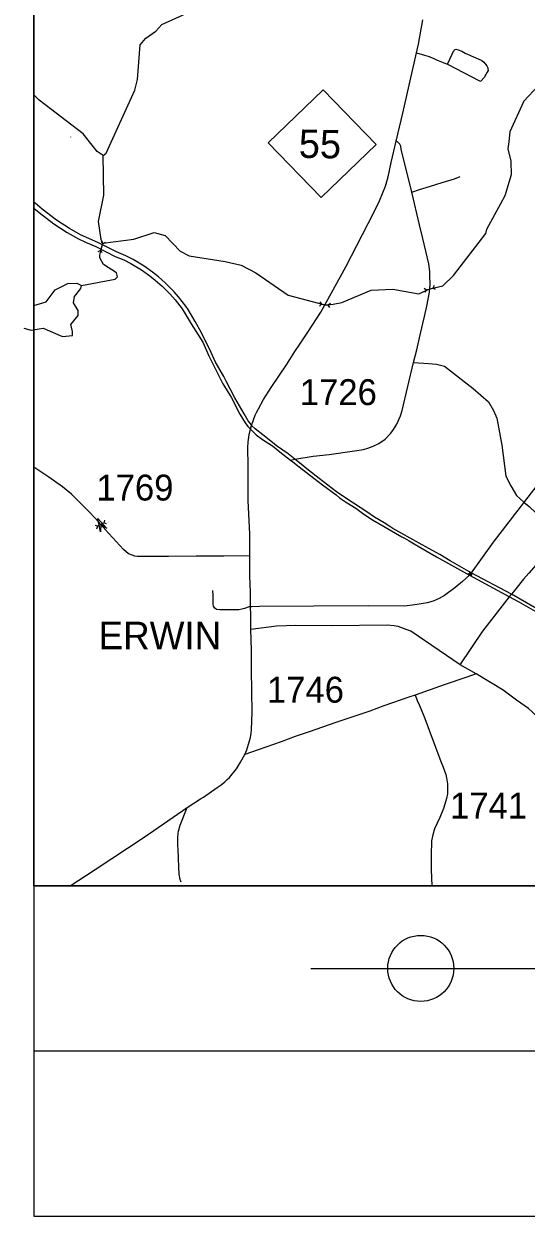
# Model space of a CAD drawing. Extents: x 0 to 2021, y 0 to 1321.
# Drawn here: x 316.9 to 408.2, y 888.1 to 1104.7 of the extents above; entities that cross this region are included whole.
import ezdxf

# ---------------------------------------------------------------- set-up
doc = ezdxf.new("R2010")
doc.units = 0
for name, color, linetype in [('Default', 7, 'Continuous'), ('Exist Hydro Stream or Body of Water', 7, 'Continuous'), ('Miscellaneous Lines', 7, 'Continuous'), ('Old_Level_26', 7, 'Continuous'), ('Scratch_Level_0', 7, 'Continuous'), ('Sheet Title CELL', 7, 'Continuous'), ('Text', 7, 'Continuous')]:
    doc.layers.add(name, color=color, linetype=linetype)

msp = doc.modelspace()

# ---------------------------------------------------------------- linework, layer by layer
at = {"layer": 'Default'}
for p, q in [((325.36, 1084.18), (325.36, 1084.13)), ((330.88, 1063.55), (331.23, 1064.72)), ((330.98, 1065.17), (331.23, 1064.72)), ((331.69, 1064.95), (331.23, 1064.72)), ((330.42, 1063.32), (330.88, 1063.55)), ((331.13, 1063.1), (330.88, 1063.55)), ((389.63, 1056.65), (390.07, 1056.38)), ((389.82, 1055.92), (390.07, 1056.38)), ((390.07, 1056.38), (391.25, 1056.68)), ((391.5, 1057.13), (391.25, 1056.68)), ((391.69, 1056.41), (391.25, 1056.68)), ((370.61, 1053.43), (371.01, 1053.75)), ((370.71, 1054.17), (371.01, 1053.75)), ((371.01, 1053.75), (372.22, 1053.58)), ((372.62, 1053.9), (372.22, 1053.58)), ((372.52, 1053.16), (372.22, 1053.58)), ((330.33, 1013.46), (331.42, 1014.02)), ((331.57, 1014.51), (331.42, 1014.02)), ((331.91, 1013.84), (331.42, 1014.02)), ((329.85, 1013.63), (330.33, 1013.46)), ((330.19, 1012.97), (330.33, 1013.46)), ((397.6, 1004.74), (397.79, 1004.76)), ((397.86, 1005.21), (397.94, 1005.04)), ((397.87, 1004.9), (398.28, 1004.67)), ((398.21, 1004.53), (398.29, 1004.36)), ((398.36, 1004.8), (398.55, 1004.82)), ((399.1, 986.58), (396.23, 988.25))]:
    msp.add_line(p, q, dxfattribs=at)
for points in [[(388.26, 1099.46), (388.6, 1101.01), (389.44, 1105.43)], [(384.57, 1083.38), (385.79, 1088.45), (388.26, 1099.46)], [(358.25, 1031.74), (358.58, 1032.59), (358.93, 1033.58), (359.2, 1034.11), (359.52, 1034.76), (360.45, 1036.46), (361.84, 1038.65), (363.34, 1040.86), (364.64, 1042.75), (366.18, 1045.15), (367.06, 1046.48), (368.61, 1048.84), (370.9, 1052.3), (375.45, 1060.53), (377.43, 1064.41), (380.49, 1070.44), (381.53, 1072.56), (382.61, 1075.22), (383.09, 1076.89), (383.68, 1079.48), (384.57, 1083.38)], [(343.97, 1056.26), (342.61, 1057.63), (341.36, 1058.73), (340.28, 1059.59), (338.74, 1060.67), (336.77, 1061.86), (335.42, 1062.55), (333.76, 1063.25), (330.34, 1065), (327.2, 1066.39), (325.22, 1067.49), (322.83, 1069.05), (320.22, 1071.05), (318.96, 1072.12), (318.71, 1072.35)], [(318.71, 1071.24), (319.7, 1070.41), (322.35, 1068.37), (324.8, 1066.78), (326.83, 1065.66), (328.08, 1065.06), (329.99, 1064.25), (333.52, 1062.44), (335.07, 1061.8), (336.37, 1061.14), (338.28, 1059.98), (339.78, 1058.93), (340.77, 1058.14), (342.04, 1057.03), (343.41, 1055.64)], [(343.41, 1055.64), (344.38, 1054.58), (345.67, 1052.9), (347.34, 1050.19), (349.43, 1046.87), (350.53, 1044.36), (352.57, 1040.26), (353.09, 1039.3), (354.58, 1036.89), (356.14, 1033.76), (357.12, 1032.18), (357.59, 1031.53), (358.08, 1031.06)], [(358.25, 1031.74), (358.03, 1032.15), (357.67, 1032.58), (356.92, 1033.86), (355.24, 1036.74), (353.71, 1039.66), (353.22, 1040.65), (351.69, 1043.34), (350.93, 1044.96), (349.19, 1048.54), (348.06, 1050.61), (346.74, 1052.78), (346.36, 1053.38), (345.02, 1055.11), (344.21, 1056.02), (343.97, 1056.26)], [(358.08, 1031.06), (358.25, 1031.74)], [(366.18, 1025.58), (364.97, 1026.6), (363.02, 1027.93), (360.31, 1030.05), (358.97, 1031.13), (358.25, 1031.74)], [(357.97, 1008.02), (357.99, 1011.97), (357.65, 1018.1), (357.66, 1019.8), (357.7, 1021.46), (357.7, 1024.38), (357.59, 1027.64), (357.64, 1028.74), (357.72, 1029.17), (357.87, 1030.05), (358.08, 1031.06)], [(358.08, 1031.06), (358.69, 1030.45), (359.14, 1030.05), (360.29, 1029.19), (362.12, 1028), (363.44, 1026.92), (365.36, 1025.45)], [(365.36, 1025.45), (366.18, 1025.58)], [(365.36, 1025.45), (365.78, 1025.12), (366.91, 1024.24), (369.6, 1022.13), (371.18, 1020.95), (373.69, 1019.14), (374.28, 1018.58), (375.39, 1017.83), (377.22, 1016.69), (378.69, 1015.61), (380.27, 1014.59), (385.61, 1011.47), (386.06, 1011.24), (386.91, 1010.77), (387.83, 1010.2), (388.9, 1009.6), (391.88, 1007.88), (395.19, 1006.03), (397.89, 1004.53), (405.18, 1000.57)], [(405.51, 1001.06), (398.23, 1004.97), (394.38, 1007.16), (392.48, 1008.26), (390.48, 1009.36), (388.74, 1010.34), (383.96, 1013), (383.44, 1013.38), (382.38, 1014.01), (380.66, 1015.09), (379.26, 1016.03), (375.63, 1018.41), (373.75, 1019.67), (372.12, 1020.9), (370.56, 1022.09), (368.63, 1023.61), (367.29, 1024.68), (366.18, 1025.58)], [(358.16, 994.64), (358.11, 1001.43), (357.97, 1004.43), (357.97, 1008.02)], [(398.23, 1004.97), (398.07, 1004.78), (397.89, 1004.53)], [(405.18, 1000.57), (405.51, 1001.06)], [(430.33, 989.73), (427.01, 990.86), (421.08, 993.12), (417.19, 994.81), (411, 997.95), (405.51, 1001.06)], [(405.18, 1000.57), (406.85, 999.66), (409.81, 998.01), (413.1, 996.25), (416.96, 994.35), (420.49, 992.77), (424.73, 991.12), (430.09, 989.18)], [(357.05, 971.93), (357.4, 972.77), (357.94, 974.42), (358.07, 975.05), (358.2, 975.84), (358.27, 976.4), (358.37, 979.66), (358.35, 983.39), (358.27, 987.38), (358.28, 990.89), (358.16, 994.64)], [(346.61, 962.28), (349, 963.89), (349.54, 964.21), (352.03, 965.94), (352.77, 966.44), (353.41, 967), (353.87, 967.41), (354.26, 967.77), (355.57, 969.33), (356.28, 970.54), (357.05, 971.93)], [(325.34, 948.09), (329.86, 951.06), (338.77, 956.9), (346.61, 962.28)]]:
    msp.add_lwpolyline(points, dxfattribs=at)
for points in [[(361.3, 1083.11), (371.28, 1092.74), (380.91, 1082.76), (370.93, 1073.13)], [(330.81, 1012.42), (330.33, 1014.85), (331.96, 1012.99), (330.88, 1013.74)], [(397.79, 1004.76), (398.21, 1004.53), (398.36, 1004.81), (397.94, 1005.04)]]:
    msp.add_lwpolyline(points, close=True, dxfattribs=at)
at = {"layer": 'Exist Hydro Stream or Body of Water'}
for points in [[(331.34, 1080.81), (331.85, 1081.23), (337.05, 1092.66), (337.55, 1094.61), (338.04, 1100.92), (339.05, 1102.13), (340.91, 1103.38), (342, 1104.56), (346.38, 1106.6), (349.92, 1109.25), (351.94, 1111.1), (355.81, 1116.27), (356.73, 1118.78), (357.39, 1124.45)], [(407.77, 1090.57), (407.8, 1090.64), (410.4, 1093.45)], [(331.34, 1080.81), (330.24, 1081.5), (327.69, 1084.71), (319.66, 1090.82), (318.71, 1091.8)], [(405.08, 1083.28), (405.28, 1085.17), (407.77, 1090.57)], [(405.47, 1079.61), (405.46, 1079.75), (404.95, 1082.02), (405.08, 1083.28)], [(331.28, 1064.88), (330.98, 1065.51), (330.44, 1068.76), (331.44, 1073.56), (331.34, 1080.81)], [(403.58, 1072.06), (404.38, 1073.52), (405.55, 1077.32), (405.47, 1079.61)], [(400.86, 1066.58), (401.02, 1067.41), (403.58, 1072.06)], [(331.28, 1064.88), (336.87, 1065.57), (340.58, 1066.82), (342.6, 1066.25), (345.32, 1063.37), (346.92, 1062.54), (353.5, 1061.54), (356.38, 1060.88), (359.09, 1059.46), (364.92, 1055.42), (371.62, 1053.66), (372.24, 1053.66), (373.09, 1053.75), (374.72, 1054.09), (380.03, 1056.3), (383.99, 1056.49), (388.68, 1055.64), (390.16, 1056.33), (390.66, 1056.53), (393.03, 1057.1), (394.97, 1058.95), (400.86, 1066.58)], [(327.35, 1057.16), (333.51, 1058.29), (333.92, 1058.72), (333.75, 1059.48), (331.39, 1061), (330.73, 1062.21), (330.69, 1062.69), (331.05, 1064.13), (331.28, 1064.88)], [(318.71, 1053.52), (320.94, 1054.2), (322.62, 1056.39), (324.9, 1057.51), (326.51, 1057.61), (327.35, 1057.16)], [(316.9, 1049.39), (318.25, 1049.03), (320.44, 1049.39), (323.91, 1047.89), (325.76, 1048.05), (325.76, 1048.81), (325.43, 1050.08), (326.77, 1051.68), (326.77, 1052.61), (325.92, 1054.03), (326.09, 1055.15), (327.27, 1056.59), (327.35, 1057.16)]]:
    msp.add_lwpolyline(points, dxfattribs=at)
at = {"layer": 'Miscellaneous Lines'}
msp.add_line((369.03, 933.08), (489.06, 933.08), dxfattribs=at)
for points in [[(435.29, 1060.84), (435.29, 1058.17), (435.16, 1056.34), (435.03, 1055.43), (434.72, 1054.3), (434.33, 1053.17), (433.94, 1052.3), (433.59, 1051.56), (433.07, 1050.64), (432.41, 1049.6), (431.85, 1048.81), (431.02, 1047.64), (424.1, 1038.81), (419.88, 1033.5), (402.18, 1010.51), (398.23, 1004.97)], [(397.89, 1004.53), (396.63, 1003.35), (395.24, 1002.23), (393.36, 1000.83), (392.36, 1000.31), (391.27, 999.79), (390.23, 999.49), (388.4, 999.18), (386.14, 998.92), (379.48, 998.93), (359.75, 998.83), (358.34, 998.8), (357.86, 998.76), (356.99, 998.46), (356.51, 998.33), (355.99, 998.24), (354.81, 998.24), (352.55, 998.2), (351.94, 998.28), (351.64, 998.5), (351.37, 998.89), (351.33, 999.24), (351.29, 999.94), (351.29, 1000.85), (351.25, 1001.72)]]:
    msp.add_lwpolyline(points, dxfattribs=at)
msp.add_ellipse((389.04, 933.08), major_axis=(0, 6), ratio=0.999692, dxfattribs=at)
at = {"layer": 'Old_Level_26'}
for points in [[(388.26, 1099.46), (389.73, 1099.02), (390.56, 1098.74), (390.78, 1098.64), (391.27, 1098.49), (392.02, 1098.12), (392.7, 1097.86), (393.22, 1097.63), (393.9, 1097.37)], [(393.9, 1097.37), (394.74, 1099.22), (394.87, 1099.48), (395.04, 1099.74), (395.11, 1099.89), (395.18, 1099.96), (395.44, 1100.1), (395.85, 1099.96), (396.48, 1099.74), (397.12, 1099.37), (397.98, 1099.02), (398.22, 1098.92)], [(398.22, 1098.92), (399.48, 1098.36), (400.15, 1098.02), (400.5, 1097.72), (401.03, 1097.07), (401.22, 1096.73), (401.22, 1096.51), (401.27, 1096.25), (401.12, 1095.94), (400.85, 1095.49), (400.59, 1094.95), (399.96, 1094.28)], [(393.9, 1097.37), (399.71, 1094.34), (399.96, 1094.28)], [(387.41, 1074.1), (385.49, 1081.93), (385.4, 1082.45), (385.23, 1082.84), (385.01, 1083.09), (384.83, 1083.24), (384.57, 1083.38)], [(387.41, 1074.1), (388.84, 1074.59), (390.84, 1075.18), (392.96, 1075.87), (395.16, 1076.53), (396.18, 1076.97)], [(387.75, 1043.16), (388.31, 1045.47), (388.8, 1047.65), (389.42, 1050.23), (389.69, 1051.54), (390.12, 1053.42), (390.39, 1054.67), (390.58, 1055.56), (390.66, 1056.53), (390.72, 1057.48), (390.71, 1058.86), (390.67, 1059.73), (390.49, 1061.09), (389.41, 1065.73), (388.79, 1068.16), (387.41, 1074.1)], [(366.18, 1025.58), (369.49, 1026.17), (372.4, 1026.47), (377, 1027.1), (378.62, 1027.36), (379.42, 1027.63), (380.38, 1027.95), (381.4, 1028.43), (382.56, 1029.22), (383.6, 1030.35), (384.1, 1030.97), (384.68, 1031.99), (385.36, 1033.49), (385.65, 1034.44), (387.75, 1043.16)], [(387.75, 1043.16), (390.46, 1042.98), (391.89, 1042.86), (393.34, 1042.53), (398.57, 1038.42), (401.34, 1036.01), (402.26, 1034.47), (402.88, 1033.06), (403.8, 1028.13), (404.53, 1022.52), (405.4, 1020.74), (406.44, 1019.01), (407.77, 1017.78)], [(357.97, 1008.02), (353.22, 1007.99), (348.2, 1007.96), (343.21, 1007.94), (338.45, 1007.89), (337.54, 1007.91), (337.09, 1007.98), (336.57, 1008.13), (335.95, 1008.41), (335.01, 1009.18), (332.36, 1012.09), (331.8, 1012.71), (330.88, 1013.74), (329.9, 1014.81), (328.64, 1016.14), (327.76, 1017.04), (326.4, 1018.41), (325.53, 1019.24), (323.9, 1020.58), (321.42, 1022.31), (319.42, 1023.69), (318.71, 1024.16)], [(407.77, 1017.78), (408.73, 1017), (414.66, 1011.34)], [(414.66, 1011.34), (413.51, 1010.2), (411.69, 1008.27), (410.43, 1006.9), (408.71, 1004.89), (407.73, 1003.79), (406.34, 1002.02), (405.86, 1001.42), (405.51, 1001.06)], [(396.23, 988.25), (400.34, 994.33), (405.18, 1000.57)], [(396.23, 988.25), (392.4, 990.84), (387.24, 994.35), (386.41, 994.67), (384.95, 995.18), (384.18, 995.31), (382.91, 995.43), (372.84, 995.31), (366.34, 995.38), (362.84, 995.25), (358.16, 994.64)], [(399.1, 986.58), (397.4, 985.97), (393.28, 984.62), (388.05, 982.72)], [(441.47, 958.47), (440.54, 959.09), (438.6, 959.81), (435.86, 960.9), (433.92, 961.73), (429.1, 963.75), (426.61, 964.84), (425.87, 965.21), (424.47, 965.96), (423.28, 966.85), (422.22, 967.8), (419.84, 969.97), (417.99, 971.65), (416.32, 973.33), (414.09, 975.2), (413.25, 975.99), (412.01, 977.1), (411.25, 977.8), (410.41, 978.55), (409.26, 979.67), (408.65, 980.3), (406.44, 981.84), (403.99, 983.62), (399.1, 986.58)], [(388.05, 982.72), (386.89, 982.36), (382.35, 980.78), (379.76, 979.81), (373.59, 977.73), (368.76, 976.04), (366.19, 975.2), (363.66, 974.25), (359.49, 972.8), (357.05, 971.93)], [(388.05, 982.72), (388.24, 982.1), (388.41, 981.78), (388.8, 980.86), (389.55, 979.06), (389.59, 978.95), (392.7, 970.66), (393.13, 969.62), (393.58, 968.31), (393.68, 968.01), (393.73, 967.68), (393.87, 966.63), (393.9, 966.1), (393.91, 965.39), (393.88, 964.82), (393.7, 963.93), (393.41, 962.89), (393.15, 962.12), (392.49, 960.49), (391.52, 958.45), (391.21, 957.34), (391.01, 956.25), (390.92, 953.58), (390.94, 951.04), (391.05, 948.09)], [(345.47, 948.76), (345.32, 949.24), (345.12, 950.2), (345.07, 951.44), (344.93, 954.76), (344.9, 955.37), (344.87, 956.51), (344.89, 956.8), (344.96, 957.66), (345.02, 957.99), (345.31, 959.11), (346.61, 962.28)]]:
    msp.add_lwpolyline(points, dxfattribs=at)
at = {"layer": 'Scratch_Level_0'}
msp.add_lwpolyline([(318.71, 1236.23), (654.77, 1236.23), (654.77, 948.09), (318.71, 948.09)], close=True, dxfattribs=at)
at = {"layer": 'Sheet Title CELL'}
for p, q in [((318.71, 1236.23), (318.71, 888.06)), ((318.71, 948.09), (654.77, 948.09)), ((318.71, 918.07), (654.77, 918.07)), ((318.71, 888.06), (654.77, 888.06))]:
    msp.add_line(p, q, dxfattribs=at)

# ---------------------------------------------------------------- texts
at = {"layer": 'Default'}
msp.add_text('55', height=5.153, rotation=358.9625, dxfattribs=at).set_placement((366.84, 1080.37))
at = {"layer": 'Text'}
for s, height, rotation, p in [('1726', 4.705, 360, (367.06, 1035.43)), ('1769', 4.705, 360, (330.09, 1018.09)), ('ERWIN', 5, 359.915, (330.48, 991.08)), ('1746', 4.705, 360, (361.08, 981.36)), ('1741', 4.705, 360, (394.37, 960.31))]:
    msp.add_text(s, height=height, rotation=rotation, dxfattribs=at).set_placement(p)

doc.saveas('drawing.dxf')
